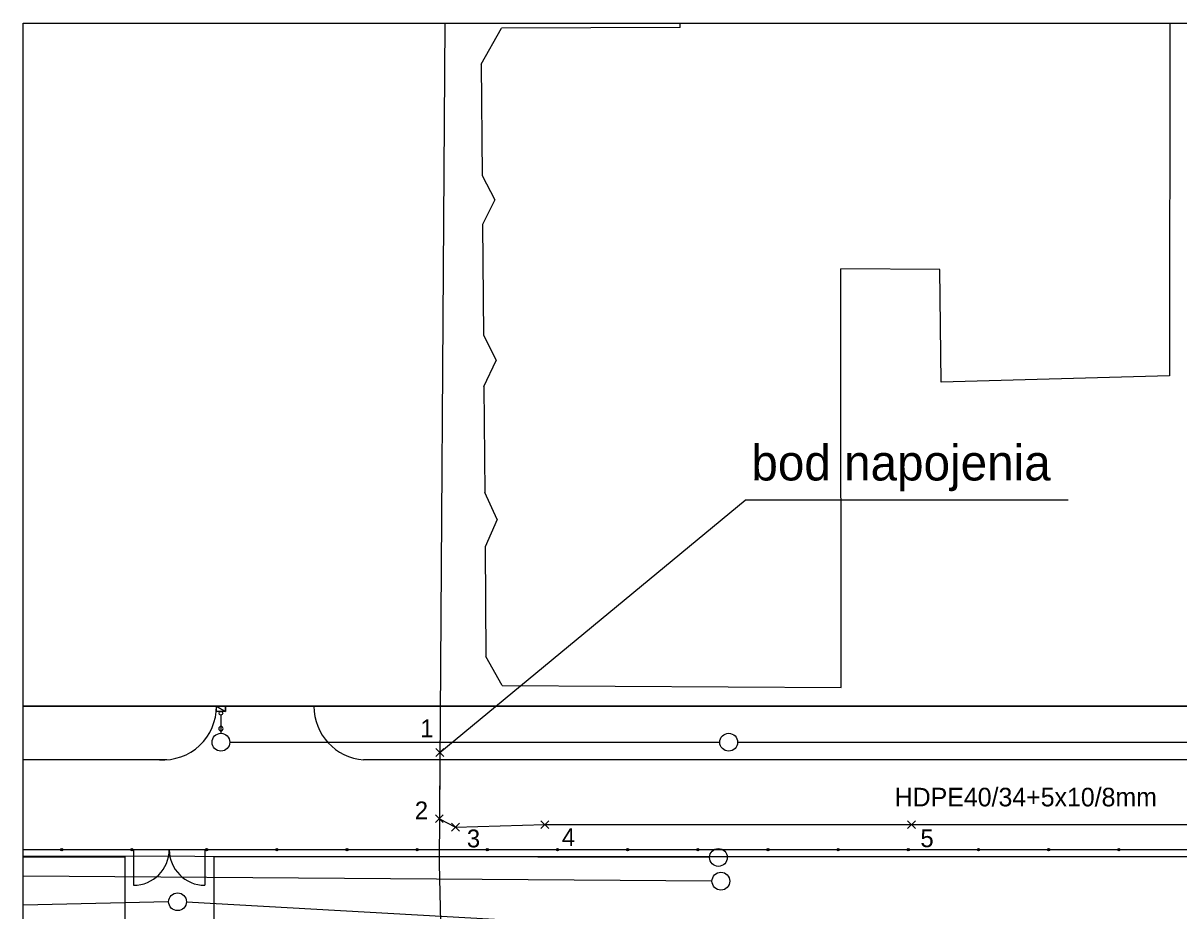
# Model space of a CAD drawing. Extents: x -264053 to -263843, y -1242290 to -1242141.
# Drawn here: x -264053.3 to -263988.4, y -1242191 to -1242141.1 of the extents above; entities that cross this region are included whole.
import ezdxf

# ---------------------------------------------------------------- set-up
doc = ezdxf.new("R2010")
doc.units = 0
for name, color, linetype in [('KFA_2D_JESTVUJUCE_IS_DSP', 7, 'Continuous'), ('KFA_2D_SITUACIA_DSP', 7, 'Continuous'), ('KFA_63-2_TELEKOM_PRIPOJKA', 7, 'Continuous'), ('KFA_BODY_CISLO', 7, 'Continuous'), ('KFA_BODY_SYMBOL', 7, 'Continuous'), ('KFA_JESTV_IS_DSP', 7, 'Continuous'), ('KFA_SITUACIA_DSP', 7, 'Continuous'), ('POPIS', 7, 'Continuous'), ('RAM_NA_TLAC_A3_1-500', 7, 'Continuous')]:
    doc.layers.add(name, color=color, linetype=linetype)

msp = doc.modelspace()

# ---------------------------------------------------------------- linework, layer by layer
at = {"layer": 'KFA_2D_JESTVUJUCE_IS_DSP'}
for p, q in [((-264029.598, -1242141.125), (-264029.913, -1242188.318)), ((-264014.738, -1242187.967), (-264053.272, -1242187.898)), ((-264029.913, -1242188.318), (-264029.719, -1242196.934)), ((-264014.599, -1242189.295), (-264053.272, -1242189.013)), ((-264045.101, -1242190.466), (-264053.272, -1242190.641)), ((-263970.367, -1242194.605), (-264044.102, -1242190.483))]:
    msp.add_line(p, q, dxfattribs=at)
for centre in [(-264014.238, -1242187.968), (-264014.099, -1242189.299), (-264044.601, -1242190.456)]:
    msp.add_circle(centre, 0.5, dxfattribs=at)
at = {"layer": 'KFA_2D_SITUACIA_DSP'}
for p, q in [((-264027.55, -1242143.43), (-264026.42, -1242141.41)), ((-264016.38, -1242141.37), (-264026.42, -1242141.41)), ((-264016.38, -1242141.37), (-264016.384, -1242141.125)), ((-263988.894, -1242141.125), (-263988.91, -1242160.93)), ((-264027.55, -1242143.43), (-264027.5, -1242149.68)), ((-264027.5, -1242149.68), (-264026.79, -1242151.05)), ((-264026.79, -1242151.05), (-264027.48, -1242152.43)), ((-264027.48, -1242152.43), (-264027.43, -1242158.63)), ((-264007.37, -1242157.14), (-264007.36, -1242154.93)), ((-264001.8, -1242154.96), (-264007.36, -1242154.93)), ((-264001.73, -1242161.29), (-264001.8, -1242154.96)), ((-264007.34, -1242178.42), (-264007.37, -1242157.14)), ((-264027.43, -1242158.63), (-264026.72, -1242160.07)), ((-264027.41, -1242161.52), (-264026.72, -1242160.07)), ((-263988.91, -1242160.93), (-264001.73, -1242161.29)), ((-264027.41, -1242161.52), (-264027.36, -1242167.48)), ((-264026.65, -1242168.99), (-264027.36, -1242167.48)), ((-264026.65, -1242168.99), (-264027.34, -1242170.52)), ((-264027.34, -1242170.52), (-264027.29, -1242176.68)), ((-264026.37, -1242178.31), (-264027.29, -1242176.68)), ((-264026.37, -1242178.31), (-264007.34, -1242178.42)), ((-263959.468, -1242179.482), (-264053.272, -1242179.482)), ((-264053.272, -1242179.482), (-263959.468, -1242179.482)), ((-263959.468, -1242179.482), (-264053.272, -1242179.482)), ((-264042.417, -1242179.482), (-264041.917, -1242179.482)), ((-264042.417, -1242179.772), (-264042.417, -1242179.482)), ((-264042.417, -1242179.482), (-264041.917, -1242179.772)), ((-264042.417, -1242179.482), (-264041.917, -1242179.772)), ((-264041.917, -1242179.482), (-264042.417, -1242179.482)), ((-264041.917, -1242179.482), (-264041.917, -1242179.772)), ((-264041.917, -1242179.772), (-264041.917, -1242179.482)), ((-264041.917, -1242179.772), (-264042.417, -1242179.772)), ((-264042.167, -1242179.972), (-264042.167, -1242181)), ((-264041.667, -1242181.5), (-264014.161, -1242181.5)), ((-264013.161, -1242181.5), (-263964.161, -1242181.5)), ((-264045.204, -1242182.482), (-264053.272, -1242182.482)), ((-263960.118, -1242182.482), (-264034.158, -1242182.482)), ((-263972.068, -1242187.532), (-264053.272, -1242187.532)), ((-264051.047, -1242187.532), (-264051.167, -1242187.532)), ((-264051.107, -1242187.592), (-264051.107, -1242187.472)), ((-264047.108, -1242187.532), (-264047.228, -1242187.532)), ((-264047.168, -1242187.592), (-264047.168, -1242187.472)), ((-264047.068, -1242187.532), (-264047.068, -1242189.532)), ((-264044.568, -1242187.532), (-264045.568, -1242187.532)), ((-264043.068, -1242187.532), (-264043.068, -1242189.532)), ((-264042.908, -1242187.532), (-264043.028, -1242187.532)), ((-264042.968, -1242187.592), (-264042.968, -1242187.472)), ((-264039.089, -1242187.532), (-264038.969, -1242187.532)), ((-264039.029, -1242187.592), (-264039.029, -1242187.472)), ((-264035.15, -1242187.532), (-264035.03, -1242187.532)), ((-264035.09, -1242187.592), (-264035.09, -1242187.472)), ((-264031.211, -1242187.532), (-264031.091, -1242187.532)), ((-264031.151, -1242187.592), (-264031.151, -1242187.472)), ((-264027.272, -1242187.532), (-264027.152, -1242187.532)), ((-264027.212, -1242187.592), (-264027.212, -1242187.472)), ((-264023.333, -1242187.532), (-264023.213, -1242187.532)), ((-264023.273, -1242187.592), (-264023.273, -1242187.472)), ((-264019.394, -1242187.532), (-264019.274, -1242187.532)), ((-264019.334, -1242187.592), (-264019.334, -1242187.472)), ((-264015.456, -1242187.532), (-264015.336, -1242187.532)), ((-264015.396, -1242187.592), (-264015.396, -1242187.472)), ((-264011.517, -1242187.532), (-264011.397, -1242187.532)), ((-264011.457, -1242187.592), (-264011.457, -1242187.472)), ((-264007.578, -1242187.532), (-264007.458, -1242187.532)), ((-264007.518, -1242187.592), (-264007.518, -1242187.472)), ((-264003.639, -1242187.532), (-264003.519, -1242187.532)), ((-264003.579, -1242187.592), (-264003.579, -1242187.472)), ((-263999.7, -1242187.532), (-263999.58, -1242187.532)), ((-263999.64, -1242187.592), (-263999.64, -1242187.472)), ((-263995.761, -1242187.532), (-263995.641, -1242187.532)), ((-263995.701, -1242187.592), (-263995.701, -1242187.472)), ((-263991.822, -1242187.532), (-263991.702, -1242187.532)), ((-263991.762, -1242187.592), (-263991.762, -1242187.472)), ((-264053.272, -1242289.625), (-264053.272, -1242187.932)), ((-264053.272, -1242187.932), (-264047.568, -1242187.932)), ((-264047.568, -1242187.932), (-264047.568, -1242289.625)), ((-263972.468, -1242187.932), (-264042.568, -1242187.932)), ((-264042.568, -1242187.932), (-264042.568, -1242289.625))]:
    msp.add_line(p, q, dxfattribs=at)
for centre, radius in [((-264042.167, -1242179.872), 0.1), ((-264042.167, -1242181.5), 0.5), ((-264013.661, -1242181.5), 0.5), ((-264051.107, -1242187.532), 0.06), ((-264047.168, -1242187.532), 0.06), ((-264042.968, -1242187.532), 0.06), ((-264039.029, -1242187.532), 0.06), ((-264035.09, -1242187.532), 0.06), ((-264031.151, -1242187.532), 0.06), ((-264027.212, -1242187.532), 0.06), ((-264023.273, -1242187.532), 0.06), ((-264019.334, -1242187.532), 0.06), ((-264015.396, -1242187.532), 0.06), ((-264011.457, -1242187.532), 0.06), ((-264007.518, -1242187.532), 0.06), ((-264003.579, -1242187.532), 0.06), ((-263999.64, -1242187.532), 0.06), ((-263995.701, -1242187.532), 0.06), ((-263991.762, -1242187.532), 0.06)]:
    msp.add_circle(centre, radius, dxfattribs=at)
for centre, radius, start, end in [((-264045.412, -1242179.495), 2.994, 266.03136, 0.25001), ((-264033.951, -1242179.495), 2.994, 179.74999, 266.03136), ((-264042.167, -1242180.736), 0.125, 0, 180), ((-264042.167, -1242180.736), 0.125, 180, 0), ((-264047.068, -1242187.532), 2, 270, 360), ((-264043.068, -1242187.532), 2, 180, 270)]:
    msp.add_arc(centre, radius, start, end, dxfattribs=at)
at = {"layer": 'KFA_63-2_TELEKOM_PRIPOJKA'}
msp.add_lwpolyline([(-264029.881, -1242182.077), (-264029.905, -1242185.793), (-264029.004, -1242186.266), (-264023.98, -1242186.128), (-264003.402, -1242186.128), (-263982.858, -1242186.12), (-263966.19, -1242185.767), (-263953.396, -1242185.506), (-263939.258, -1242185.468), (-263919.631, -1242185.484), (-263914.168, -1242185.372)], dxfattribs=at)
at = {"layer": 'KFA_BODY_SYMBOL'}
for p, q in [((-264030.102, -1242182.298), (-264029.66, -1242181.856)), ((-264029.66, -1242182.298), (-264030.102, -1242181.856)), ((-264030.126, -1242186.014), (-264029.684, -1242185.572)), ((-264029.684, -1242186.014), (-264030.126, -1242185.572)), ((-264029.225, -1242186.487), (-264028.783, -1242186.045)), ((-264028.783, -1242186.487), (-264029.225, -1242186.045)), ((-264024.201, -1242186.349), (-264023.759, -1242185.907)), ((-264023.759, -1242186.349), (-264024.201, -1242185.907)), ((-264003.623, -1242186.349), (-264003.181, -1242185.907)), ((-264003.181, -1242186.349), (-264003.623, -1242185.907))]:
    msp.add_line(p, q, dxfattribs=at)
at = {"layer": 'KFA_JESTV_IS_DSP'}
for p, q in [((-264014.738, -1242187.967), (-264053.272, -1242187.898)), ((-264014.599, -1242189.295), (-264053.272, -1242189.013)), ((-264045.101, -1242190.466), (-264053.272, -1242190.641)), ((-263970.367, -1242194.605), (-264044.102, -1242190.483))]:
    msp.add_line(p, q, dxfattribs=at)
for centre in [(-264014.238, -1242187.968), (-264014.099, -1242189.299), (-264044.601, -1242190.456)]:
    msp.add_circle(centre, 0.5, dxfattribs=at)
at = {"layer": 'KFA_SITUACIA_DSP'}
for p, q in [((-264027.55, -1242143.43), (-264026.42, -1242141.41)), ((-264016.38, -1242141.37), (-264026.42, -1242141.41)), ((-264016.38, -1242141.37), (-264016.384, -1242141.125)), ((-263988.894, -1242141.125), (-263988.91, -1242160.93)), ((-264027.55, -1242143.43), (-264027.5, -1242149.68)), ((-264027.5, -1242149.68), (-264026.79, -1242151.05)), ((-264026.79, -1242151.05), (-264027.48, -1242152.43)), ((-264027.48, -1242152.43), (-264027.43, -1242158.63)), ((-264007.37, -1242157.14), (-264007.36, -1242154.93)), ((-264001.8, -1242154.96), (-264007.36, -1242154.93)), ((-264001.73, -1242161.29), (-264001.8, -1242154.96)), ((-264007.34, -1242178.42), (-264007.37, -1242157.14)), ((-264027.43, -1242158.63), (-264026.72, -1242160.07)), ((-264027.41, -1242161.52), (-264026.72, -1242160.07)), ((-263988.91, -1242160.93), (-264001.73, -1242161.29)), ((-264027.41, -1242161.52), (-264027.36, -1242167.48)), ((-264026.65, -1242168.99), (-264027.36, -1242167.48)), ((-264026.65, -1242168.99), (-264027.34, -1242170.52)), ((-264027.34, -1242170.52), (-264027.29, -1242176.68)), ((-264026.37, -1242178.31), (-264027.29, -1242176.68)), ((-264026.37, -1242178.31), (-264007.34, -1242178.42)), ((-263959.468, -1242179.482), (-264053.272, -1242179.482)), ((-264053.272, -1242179.482), (-263959.468, -1242179.482)), ((-263959.468, -1242179.482), (-264053.272, -1242179.482)), ((-264042.417, -1242179.482), (-264041.917, -1242179.482)), ((-264042.417, -1242179.772), (-264042.417, -1242179.482)), ((-264042.417, -1242179.482), (-264041.917, -1242179.772)), ((-264042.417, -1242179.482), (-264041.917, -1242179.772)), ((-264041.917, -1242179.482), (-264042.417, -1242179.482)), ((-264041.917, -1242179.482), (-264041.917, -1242179.772)), ((-264041.917, -1242179.772), (-264041.917, -1242179.482)), ((-264041.917, -1242179.772), (-264042.417, -1242179.772)), ((-264042.167, -1242179.972), (-264042.167, -1242181)), ((-264041.667, -1242181.5), (-264014.161, -1242181.5)), ((-264013.161, -1242181.5), (-263964.161, -1242181.5)), ((-264045.204, -1242182.482), (-264053.272, -1242182.482)), ((-263960.118, -1242182.482), (-264034.158, -1242182.482)), ((-263972.068, -1242187.532), (-264053.272, -1242187.532)), ((-264051.047, -1242187.532), (-264051.167, -1242187.532)), ((-264051.107, -1242187.592), (-264051.107, -1242187.472)), ((-264047.108, -1242187.532), (-264047.228, -1242187.532)), ((-264047.168, -1242187.592), (-264047.168, -1242187.472)), ((-264047.068, -1242187.532), (-264047.068, -1242189.532)), ((-264044.568, -1242187.532), (-264045.568, -1242187.532)), ((-264043.068, -1242187.532), (-264043.068, -1242189.532)), ((-264042.908, -1242187.532), (-264043.028, -1242187.532)), ((-264042.968, -1242187.592), (-264042.968, -1242187.472)), ((-264039.089, -1242187.532), (-264038.969, -1242187.532)), ((-264039.029, -1242187.592), (-264039.029, -1242187.472)), ((-264035.15, -1242187.532), (-264035.03, -1242187.532)), ((-264035.09, -1242187.592), (-264035.09, -1242187.472)), ((-264031.211, -1242187.532), (-264031.091, -1242187.532)), ((-264031.151, -1242187.592), (-264031.151, -1242187.472)), ((-264027.272, -1242187.532), (-264027.152, -1242187.532)), ((-264027.212, -1242187.592), (-264027.212, -1242187.472)), ((-264023.333, -1242187.532), (-264023.213, -1242187.532)), ((-264023.273, -1242187.592), (-264023.273, -1242187.472)), ((-264019.394, -1242187.532), (-264019.274, -1242187.532)), ((-264019.334, -1242187.592), (-264019.334, -1242187.472)), ((-264015.456, -1242187.532), (-264015.336, -1242187.532)), ((-264015.396, -1242187.592), (-264015.396, -1242187.472)), ((-264011.517, -1242187.532), (-264011.397, -1242187.532)), ((-264011.457, -1242187.592), (-264011.457, -1242187.472)), ((-264007.578, -1242187.532), (-264007.458, -1242187.532)), ((-264007.518, -1242187.592), (-264007.518, -1242187.472)), ((-264003.639, -1242187.532), (-264003.519, -1242187.532)), ((-264003.579, -1242187.592), (-264003.579, -1242187.472)), ((-263999.7, -1242187.532), (-263999.58, -1242187.532)), ((-263999.64, -1242187.592), (-263999.64, -1242187.472)), ((-263995.761, -1242187.532), (-263995.641, -1242187.532)), ((-263995.701, -1242187.592), (-263995.701, -1242187.472)), ((-263991.822, -1242187.532), (-263991.702, -1242187.532)), ((-263991.762, -1242187.592), (-263991.762, -1242187.472)), ((-264053.272, -1242289.625), (-264053.272, -1242187.932)), ((-264053.272, -1242187.932), (-264047.568, -1242187.932)), ((-264047.568, -1242187.932), (-264047.568, -1242289.625)), ((-263972.468, -1242187.932), (-264042.568, -1242187.932)), ((-264042.568, -1242187.932), (-264042.568, -1242289.625))]:
    msp.add_line(p, q, dxfattribs=at)
for centre, radius in [((-264042.167, -1242179.872), 0.1), ((-264042.167, -1242181.5), 0.5), ((-264013.661, -1242181.5), 0.5), ((-264051.107, -1242187.532), 0.06), ((-264047.168, -1242187.532), 0.06), ((-264042.968, -1242187.532), 0.06), ((-264039.029, -1242187.532), 0.06), ((-264035.09, -1242187.532), 0.06), ((-264031.151, -1242187.532), 0.06), ((-264027.212, -1242187.532), 0.06), ((-264023.273, -1242187.532), 0.06), ((-264019.334, -1242187.532), 0.06), ((-264015.396, -1242187.532), 0.06), ((-264011.457, -1242187.532), 0.06), ((-264007.518, -1242187.532), 0.06), ((-264003.579, -1242187.532), 0.06), ((-263999.64, -1242187.532), 0.06), ((-263995.701, -1242187.532), 0.06), ((-263991.762, -1242187.532), 0.06)]:
    msp.add_circle(centre, radius, dxfattribs=at)
for centre, radius, start, end in [((-264045.412, -1242179.495), 2.994, 266.03136, 0.25001), ((-264033.951, -1242179.495), 2.994, 179.74999, 266.03136), ((-264042.167, -1242180.736), 0.125, 0, 180), ((-264042.167, -1242180.736), 0.125, 180, 0), ((-264047.068, -1242187.532), 2, 270, 360), ((-264043.068, -1242187.532), 2, 180, 270)]:
    msp.add_arc(centre, radius, start, end, dxfattribs=at)
at = {"layer": 'POPIS'}
for p in [(-264029.872, -1242182.075), (-263994.597, -1242167.902)]:
    msp.add_line(p, (-264012.738, -1242167.902), dxfattribs=at)
at = {"layer": 'RAM_NA_TLAC_A3_1-500'}
msp.add_lwpolyline([(-264053.272, -1242141.125), (-263843.272, -1242141.125), (-263843.272, -1242289.625), (-264053.272, -1242289.625)], close=True, dxfattribs=at)

# ---------------------------------------------------------------- texts
at = {"layer": 'KFA_BODY_CISLO'}
for s, p in [('1', (-264030.977, -1242181.22)), ('2', (-264031.282, -1242185.827)), ('3', (-264028.359, -1242187.402)), ('4', (-264023.024, -1242187.327)), ('5', (-264002.898, -1242187.391))]:
    msp.add_text(s, height=1, dxfattribs=at).set_placement(p)
at = {"layer": 'POPIS'}
for s, height, p in [('bod napojenia', 2, (-264012.389, -1242166.804)), ('HDPE40/34+5x10/8mm', 1.045, (-264004.341, -1242185.102))]:
    msp.add_text(s, height=height, dxfattribs=at).set_placement(p)

doc.saveas('drawing.dxf')
